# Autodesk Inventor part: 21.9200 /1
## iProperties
Created: 2008-10
Part Number: 21.9200 /1
Material: UHMW, Black
Document SubType Name: Modeling
Designer: Administrator
Density: 0.94 g/cm^3
Mass: 11.9184 g
Surface Area: 60.9586 cm^2
Volume: 12.6791 cm^3
Stock Number: 22.1041 PARALLEL SLIDE BAR
Description: L = 1.5", MACHINE TO 21.9200/1
Vendor: F
Author: Administrator
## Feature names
1. Extrusion1
2. Extrusion2
3. Hole1
4. Extrusion3
